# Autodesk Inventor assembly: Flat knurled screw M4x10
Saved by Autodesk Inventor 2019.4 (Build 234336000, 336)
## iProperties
Created: 2021-08
Part Number: Flat knurled screw M4x10
Document SubType Name: Assembly
Designer: Administrator
Title: Flat knurled screw M4x10 v5
Author: Administrator
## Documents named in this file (2)
- c:\worker\convert-fusion-r06\tmp\job-1\20\output\files\f01db8e3-9ba6-469c-91a4-18b8ab1b818d\Flat knurled screw M4x10 v5_1.iam
- c:\worker\convert-fusion-r06\tmp\job-1\20\output\files\f01db8e3-9ba6-469c-91a4-18b8ab1b818d\_Flat knurled screw DIN 653-M4-10-ZB.ipt
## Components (1 placed, 1 different names)
1. _Flat knurled screw DIN 653-M4-10-ZB:1
